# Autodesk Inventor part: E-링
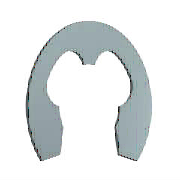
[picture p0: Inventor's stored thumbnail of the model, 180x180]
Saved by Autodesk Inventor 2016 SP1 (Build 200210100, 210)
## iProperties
IsCustomPart: 1
Created: 2012-02
Part Number: E-링
Material: 강철, 연강
Description: 리테이닝 링에 대한 사양- 탄소강 E 클립
Document SubType Name: Modeling
Standard: BS 3673-2
Designer: mduedu
Standards Organization: BSI
Language: ko-KR
Size Designation: 032MS
Categories: <MemberInstance><Categories><Category DisplayName="샤프트 부품" InternalName="7f7aeb1f-a693-4053-b835-cee3144e0d98" Mnemonic="SHFT"><Category DisplayName="써클립" Inter
Density: 1 g/cm^3
Appearance: 파란색 - 벽 페인트 - 광택
Author: mduedu
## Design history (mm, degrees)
sketch "스케치1"
  geometry: L1 (-0.4, 0.024)-(0, 0.024) reference; L2 (-3.206, 0)-(3.486, 0) reference; L3 (-1.833, -2.776)-(1.833, -2.776); L4 (0, 1.949)-(0, -3.479) reference; L5 (-2.4, -1.176)-(-2.008, -1.176); L6 (-0.4, 0.424)-(-0.4, 0.812); L7 (0, 1.524)-(2.53, 1.524); L8 (-1.833, -2.776)-(-2.096, -3.394); L9 (0, 0.024)-(-1.278, 0.024); L10 (1.833, -2.776)-(2.096, -3.394); L11 (2.4, -1.176)-(2.008, -1.176); L12 (0.4, 0.424)-(0.4, 0.812); C1 r 2 at (0, -1.976); A1 r 2 centre (0, -1.976) between (-1.894, -1.335) and (-1.833, -2.776); A2 r 0.4 centre (0, 0.424) between (-0.4, 0.424) and (0.4, 0.424); A3 r 3.5 centre (0, -1.976) between (3.196, -3.403) and (-3.196, -3.403); A4 r 3.2 centre (0, -1.976) between (-0.8, 1.122) and (-2.824, -0.47); A5 r 0.32 centre (-0.72, 0.812) between (-0.4, 0.812) and (-0.8, 1.122); A6 r 0.48 centre (-2.4, -0.696) between (-2.824, -0.47) and (-2.4, -1.176); A7 r 0.12 centre (-2.008, -1.296) between (-1.894, -1.335) and (-2.008, -1.176); A8 r 0.6 centre (-2.648, -3.158) between (-3.196, -3.403) and (-2.096, -3.394); A9 r 0.6 centre (2.648, -3.158) between (2.096, -3.394) and (3.196, -3.403); A10 r 2 centre (0, -1.976) between (1.833, -2.776) and (1.894, -1.335); A11 r 0.12 centre (2.008, -1.296) between (2.008, -1.176) and (1.894, -1.335); A12 r 0.48 centre (2.4, -0.696) between (2.4, -1.176) and (2.824, -0.47); A13 r 3.2 centre (0, -1.976) between (2.824, -0.47) and (0.8, 1.122); A14 r 0.32 centre (0.72, 0.812) between (0.8, 1.122) and (0.4, 0.812); 1 further point
  constraints: 30 point on circle, 20 end point, 15 centre point, 13 symmetric about line, 12 tangent, 8 point on line, 4 parallel, 2 coincident, 2 horizontal, 1 concentric, 1 perpendicular, 1 vertical alignment, 9 other
  dimensions: "d0" = 4 diameter of C1 (= WD); "d3" = 0.8 distance from line of A1.centre L3 (= 0.2 x ND); "d4" = 0.4 radius of A2 (= 0.1 x ND); "d5" = 7 diameter of A3 (= SD2); "d8" = 3.2 radius of A4 (= 0.8 x ND); "d9" = 0.8 distance from line of A1.centre L5 (= 0.2 x ND); "d10" = 0.32 radius of A5 (= 0.08 x ND); "d11" = 0.48 radius of A6 (= 0.12 x ND); "d12" = 0.12 radius of A7 (= 0.03 x ND); "d13" = 0.6 radius of A8 (= 0.15 x ND); "d14" = 2 distance from line of A1.centre L9 (= 0.5 x ND); "d15" = 2 radius of A1 (= 0.5 x ND)
extrude "본체" new body sketch "스케치1" distance "d16" = 0.62 (= SD); taper "d17" = 0 deg
workaxis "Work Axis1"
workaxis "Work Axis2"
workplane "Work Plane1"
body "Solid1"
other parameters: "ND" = 4 [user parameter; used in 14 equation terms], "SD" = 0.62 [user parameter; used in 1 equation term], "WD" = 4 (= WDMIN) [user parameter; used in 1 equation term], "d1" = 6.4 (= 1.6 x ND), "d2" = 4 (= ND), "SD2" = 7 [user parameter; used in 1 equation term], "d6" = 4 (= ND), "d7" = 0.6 (= 0.15 x ND), "d18" = 0, "d19" = 0, "d27" = 0, "d28" = 0, "WDMIN" = 4 [user parameter; used in 1 equation term], "SNB" = 0.67 [user parameter], "WDMAX" = 5 [user parameter], "BUBRMI" = 1 [user parameter]
